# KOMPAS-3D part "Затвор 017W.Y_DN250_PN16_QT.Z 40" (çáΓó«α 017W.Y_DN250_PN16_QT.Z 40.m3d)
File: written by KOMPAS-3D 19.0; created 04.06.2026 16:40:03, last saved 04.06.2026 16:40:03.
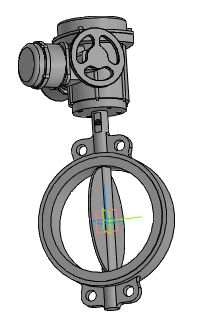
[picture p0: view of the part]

Document properties: Автор: Энергия; Полное имя файла: ..\..\..\3d для проектировщиков\017W разные\x.x Тип 017W.Y(S) Затвор дисковый поворотный межфланцевый\Затвор 017W.Y(S)_DN32-DN450_QT.Z\Затвор 017W.Y_DN250_PN16_QT.Z 40.a3d

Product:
- Part/product: Затвор 017W.Y_DN250_PN16_QT.Z 40
    Масса: 63.9353

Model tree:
1. Операция без истории:1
